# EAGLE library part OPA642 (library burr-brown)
Operational Amplifier Wideband, Low Distortion
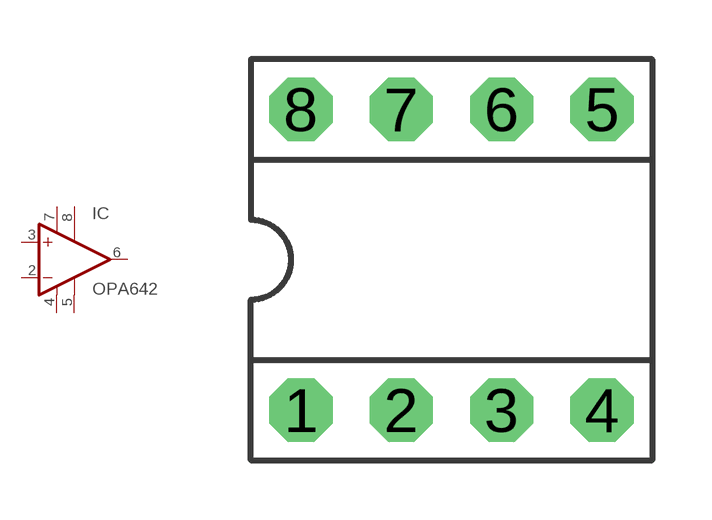
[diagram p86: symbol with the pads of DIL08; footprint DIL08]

Designator prefix IC

## OPA642P (MPN: AD9631ANZ; OC_FARNELL: unknown; OC_NEWARK: 19M1012)  [DIL08]
2  -IN  in
3  +IN  in
4  -VS1  pwr
5  -VS2  pwr
6  OUT  out
7  +VS1  pwr
8  +VS2  pwr

## Footprint DIL08 (pad centres in mm)
Dual In Line
drill 0.813 pad 1.6 octagon: 1 -3.81,-3.81; 2 -1.27,-3.81; 3 1.27,-3.81; 4 3.81,-3.81; 5 3.81,3.81; 6 1.27,3.81; 7 -1.27,3.81; 8 -3.81,3.81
